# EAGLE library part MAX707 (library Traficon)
WATCHDOG
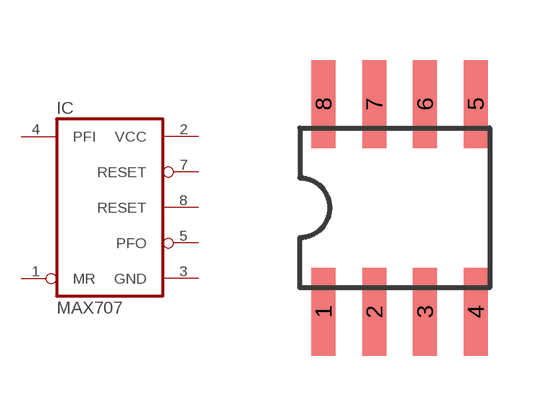
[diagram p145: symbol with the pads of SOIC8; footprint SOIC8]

Designator prefix IC

## MAX707ESA  [SOIC8]
1  MR  in
2  VCC  pwr
3  GND  pwr
4  PFI  in
5  PFO  out
7  RESET  out
8  RESET  out

## Footprint SOIC8 (pad centres in mm)
Small Outline IC
smd 0.6 x 2.2: 1 -1.905,-2.6; 2 -0.635,-2.6; 3 0.635,-2.6; 4 1.905,-2.6; 5 1.905,2.6; 6 0.635,2.6; 7 -0.635,2.6; 8 -1.905,2.6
